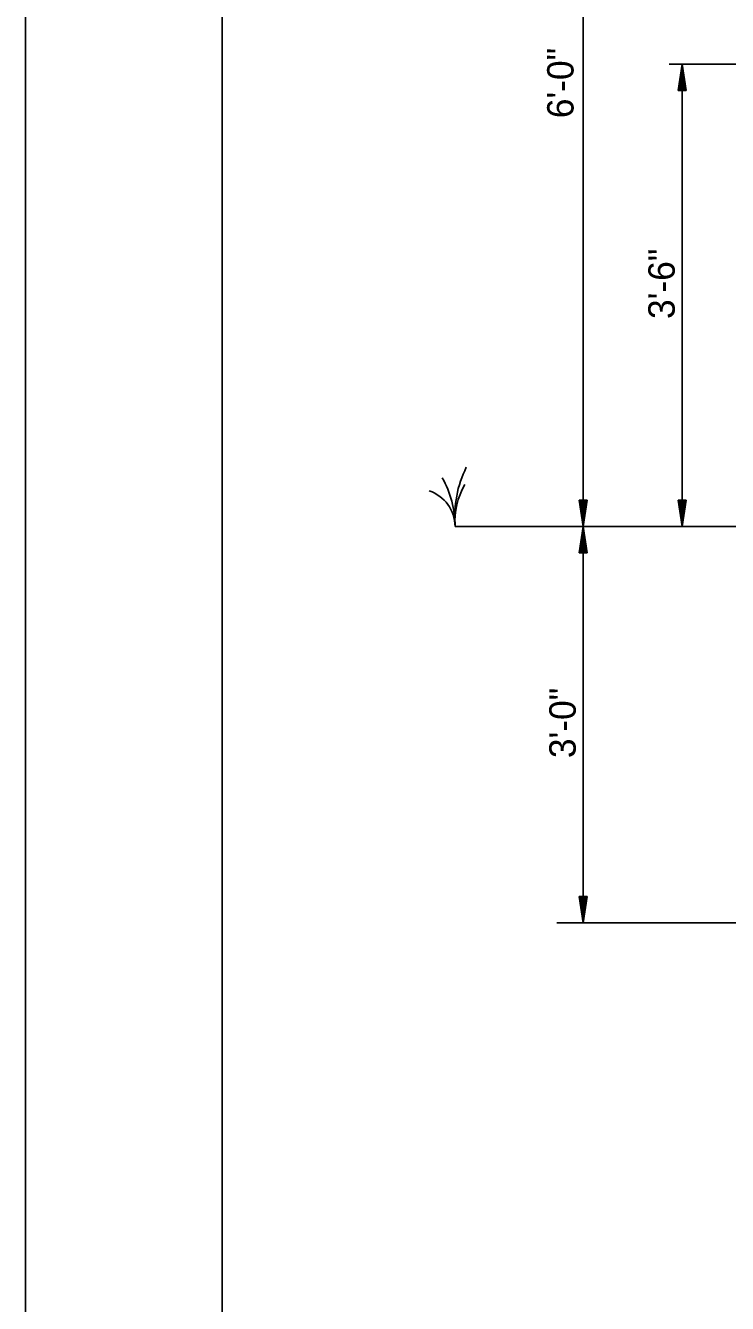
# Model space of a CAD drawing. Extents: x 1370140 to 1371141, y 380020 to 380660.
# Drawn here: x 1370140.5 to 1370273.3, y 380285.7 to 380527.5 of the extents above; entities that cross this region are included whole.
import ezdxf

# ---------------------------------------------------------------- set-up
doc = ezdxf.new("R2010")
doc.units = 0
for name, color, linetype in [('R_Border', 7, 'Continuous'), ('R_Draft', 7, 'Continuous'), ('R_No Plot', 7, 'Continuous')]:
    doc.layers.add(name, color=color, linetype=linetype)

msp = doc.modelspace()

# ---------------------------------------------------------------- linework, layer by layer
at = {"layer": 'R_Border'}
msp.add_line((1370177.71, 380031.98), (1370177.71, 380648.36), dxfattribs=at)
at = {"layer": 'R_Draft'}
for p, q in [((1370246.03, 380432.73), (1370246.03, 380586.73)), ((1370262.28, 380520.23), (1370295.6, 380520.23)), ((1370264.03, 380515.23), (1370264.78, 380520.23)), ((1370264.16, 380515.23), (1370264.78, 380519.4)), ((1370264.78, 380432.73), (1370264.78, 380520.23)), ((1370265.53, 380515.23), (1370264.78, 380520.23)), ((1370265.41, 380515.23), (1370264.78, 380519.4)), ((1370264.29, 380515.23), (1370264.78, 380518.54)), ((1370264.41, 380515.23), (1370264.78, 380517.71)), ((1370264.54, 380515.23), (1370264.78, 380516.86)), ((1370265.28, 380515.23), (1370264.78, 380518.54)), ((1370265.16, 380515.23), (1370264.78, 380517.71)), ((1370265.03, 380515.23), (1370264.78, 380516.86)), ((1370264.03, 380515.23), (1370265.53, 380515.23)), ((1370264.67, 380515.23), (1370264.78, 380516.02)), ((1370264.9, 380515.23), (1370264.78, 380516.02)), ((1370245.28, 380437.73), (1370246.03, 380432.73)), ((1370246.78, 380437.73), (1370245.28, 380437.73)), ((1370245.41, 380437.73), (1370246.03, 380433.57)), ((1370245.54, 380437.73), (1370246.03, 380434.43)), ((1370245.66, 380437.73), (1370246.03, 380435.26)), ((1370245.79, 380437.73), (1370246.03, 380436.11)), ((1370245.92, 380437.73), (1370246.03, 380436.94)), ((1370246.78, 380437.73), (1370246.03, 380432.73)), ((1370246.28, 380437.73), (1370246.03, 380436.11)), ((1370246.53, 380437.73), (1370246.03, 380434.43)), ((1370246.66, 380437.73), (1370246.03, 380433.57)), ((1370246.41, 380437.73), (1370246.03, 380435.26)), ((1370246.15, 380437.73), (1370246.03, 380436.94)), ((1370264.03, 380437.73), (1370264.78, 380432.73)), ((1370265.53, 380437.73), (1370264.03, 380437.73)), ((1370264.16, 380437.73), (1370264.78, 380433.57)), ((1370264.29, 380437.73), (1370264.78, 380434.43)), ((1370264.41, 380437.73), (1370264.78, 380435.26)), ((1370264.54, 380437.73), (1370264.78, 380436.11)), ((1370264.67, 380437.73), (1370264.78, 380436.94)), ((1370265.53, 380437.73), (1370264.78, 380432.73)), ((1370265.03, 380437.73), (1370264.78, 380436.11)), ((1370265.28, 380437.73), (1370264.78, 380434.43)), ((1370265.41, 380437.73), (1370264.78, 380433.57)), ((1370265.16, 380437.73), (1370264.78, 380435.26)), ((1370264.9, 380437.73), (1370264.78, 380436.94)), ((1370221.8, 380432.73), (1370486.02, 380432.73)), ((1370245.28, 380427.73), (1370246.03, 380432.73)), ((1370246.03, 380357.73), (1370246.03, 380432.73)), ((1370246.78, 380427.73), (1370246.03, 380432.73)), ((1370245.41, 380427.73), (1370246.03, 380431.9)), ((1370245.54, 380427.73), (1370246.03, 380431.04)), ((1370245.66, 380427.73), (1370246.03, 380430.21)), ((1370246.66, 380427.73), (1370246.03, 380431.9)), ((1370246.53, 380427.73), (1370246.03, 380431.04)), ((1370246.41, 380427.73), (1370246.03, 380430.21)), ((1370245.28, 380427.73), (1370246.78, 380427.73)), ((1370245.79, 380427.73), (1370246.03, 380429.36)), ((1370245.92, 380427.73), (1370246.03, 380428.52)), ((1370246.28, 380427.73), (1370246.03, 380429.36)), ((1370246.15, 380427.73), (1370246.03, 380428.52)), ((1370245.28, 380362.73), (1370246.03, 380357.73)), ((1370246.78, 380362.73), (1370245.28, 380362.73)), ((1370245.41, 380362.73), (1370246.03, 380358.57)), ((1370245.54, 380362.73), (1370246.03, 380359.43)), ((1370245.66, 380362.73), (1370246.03, 380360.26)), ((1370245.79, 380362.73), (1370246.03, 380361.11)), ((1370245.92, 380362.73), (1370246.03, 380361.94)), ((1370246.78, 380362.73), (1370246.03, 380357.73)), ((1370246.28, 380362.73), (1370246.03, 380361.11)), ((1370246.53, 380362.73), (1370246.03, 380359.43)), ((1370246.66, 380362.73), (1370246.03, 380358.57)), ((1370246.41, 380362.73), (1370246.03, 380360.26)), ((1370246.15, 380362.73), (1370246.03, 380361.94)), ((1370241.03, 380357.73), (1370283.22, 380357.73))]:
    msp.add_line(p, q, dxfattribs=at)
for centre, radius, start, end in [((1370202.67, 380432.6), 19.13, 0.407, 29.2294), ((1370242.77, 380434.58), 21.05, 153.6036, 185.017), ((1370214.56, 380432.61), 7.24, 1.0116, 71.214), ((1370235.07, 380433.82), 13.31, 149.1449, 184.6717)]:
    msp.add_arc(centre, radius, start, end, dxfattribs=at)
at = {"layer": 'R_No Plot'}
msp.add_lwpolyline([(1370140.49, 380660.04), (1371140.51, 380660.04), (1371140.51, 380020.03), (1370140.49, 380020.03)], close=True, dxfattribs=at)

# ---------------------------------------------------------------- texts
at = {"layer": 'R_Draft'}
for s, p in [('6\'-0"', (1370244.21, 380509.99)), ('3\'-6"', (1370263.36, 380471.99)), ('3\'-0"', (1370244.62, 380388.89))]:
    msp.add_text(s, height=5, rotation=90, dxfattribs=at).set_placement(p)

doc.saveas('drawing.dxf')
